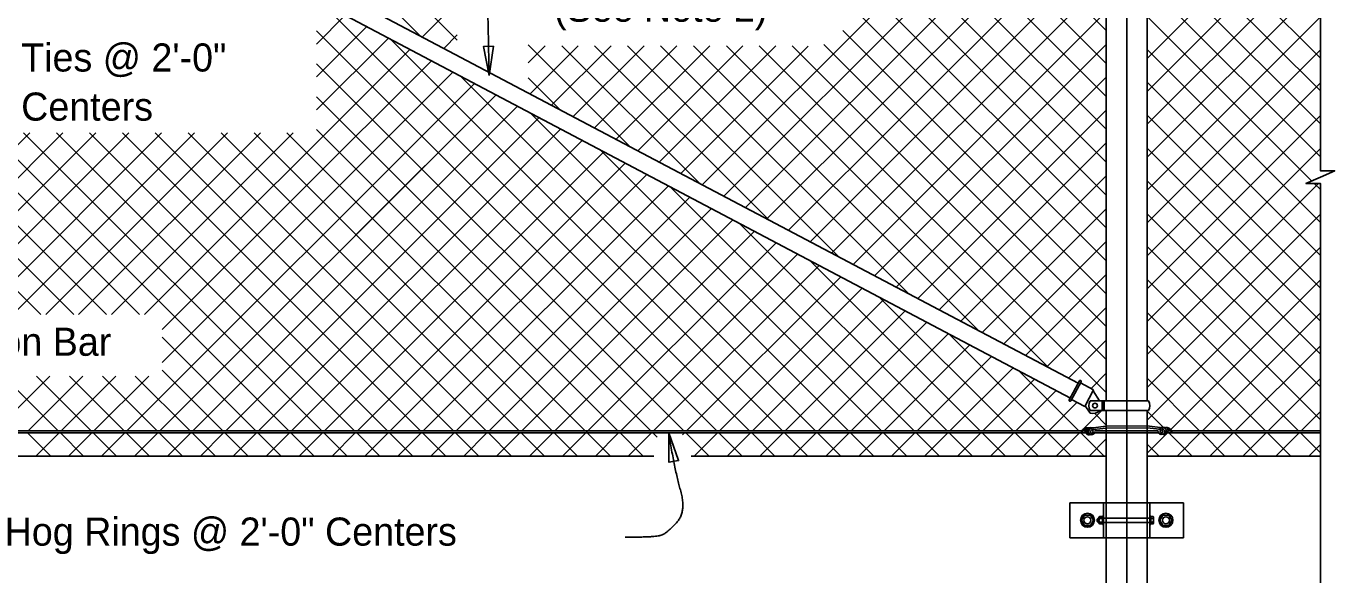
# Model space of a CAD drawing. Extents: x 0 to 41.1, y 0 to 25.9.
# Drawn here: x 6.74 to 16.11, y 16.37 to 20.31 of the extents above; entities that cross this region are included whole.
import ezdxf

# ---------------------------------------------------------------- set-up
doc = ezdxf.new("R2010")
doc.units = 0
for name, color, linetype in [('CL_Major', 7, 'Continuous'), ('Dimension', 7, 'Continuous'), ('Miscellaneous', 7, 'Continuous'), ('SteelMisc', 7, 'Continuous'), ('SteelMisc_h', 7, 'Continuous'), ('SupstrConc', 7, 'Continuous'), ('TextStructures', 7, 'Continuous')]:
    doc.layers.add(name, color=color, linetype=linetype)

msp = doc.modelspace()

# ---------------------------------------------------------------- linework, layer by layer
at = {"layer": 'CL_Major'}
msp.add_line((14.615, 25.0052), (14.615, 14.7584), dxfattribs=at)
at = {"layer": 'Dimension'}
for points in [[(16.002, 23.2265), (16.002, 21.2702), (16.1053, 21.2702), (16.002, 21.2252), (15.8987, 21.1802), (16.002, 21.1802), (16.002, 20.2867)], [(16.002, 20.2867), (16.002, 19.2689), (16.1053, 19.2689), (16.002, 19.2239), (15.8987, 19.1789), (16.002, 19.1789), (16.002, 16.9746)], [(16.002, 17.2246), (16.002, 15.3737), (16.1053, 15.3737), (16.002, 15.3287), (15.8987, 15.2837), (16.002, 15.2837), (16.002, 12.9339)]]:
    msp.add_lwpolyline(points, dxfattribs=at)
for points in [[(10.0503, 19.9529), (10.0815, 20.1618), (10.011, 20.1604)], [(11.336, 17.3912), (11.3376, 17.18), (11.4071, 17.1923)]]:
    msp.add_lwpolyline(points, close=True, dxfattribs=at)
for points in [[(6.6174, 20.081), (6.4865, 20.0669), (6.3036, 20.1341), (6.3121, 20.4608), (6.945, 21.4806)], [(10.4281, 20.8052), (10.1586, 20.8133), (10.0405, 20.6549), (10.0376, 20.5337), (10.0422, 20.3659), (10.0503, 19.9529)], [(11.0247, 16.6442), (11.2476, 16.6407), (11.3325, 16.6797), (11.4633, 16.8284), (11.3785, 17.1258), (11.336, 17.3911)]]:
    msp.add_open_spline(points, degree=2, dxfattribs=at)
at = {"layer": 'Miscellaneous'}
for p, q in [((6.7499, 23.0431), (9.5571, 20.2359)), ((6.9856, 23.0431), (9.8224, 20.2063)), ((10.5211, 23.0431), (14.4692, 19.095)), ((10.7568, 23.0431), (14.4692, 19.3307)), ((10.9925, 23.0431), (14.4692, 19.5664)), ((11.2282, 23.0431), (14.4692, 19.8021)), ((11.4639, 23.0431), (14.4692, 20.0378)), ((11.6996, 23.0431), (14.4692, 20.2735)), ((11.5767, 19.1686), (14.4692, 22.0611)), ((11.7309, 19.0871), (14.4692, 21.8254)), ((11.8851, 19.0056), (14.4692, 21.5897)), ((12.0393, 18.9241), (14.4692, 21.354)), ((14.7609, 21.318), (16.002, 20.0769)), ((14.7609, 20.0738), (16.002, 21.3149)), ((4.8859, 21.1359), (8.6158, 17.4059)), ((12.1936, 18.8426), (14.4692, 21.1183)), ((14.7609, 21.0823), (16.002, 19.8412)), ((14.7609, 19.8381), (16.002, 21.0792)), ((4.8859, 20.9002), (7.5472, 18.2388)), ((12.3478, 18.7611), (14.4692, 20.8826)), ((14.7609, 20.8466), (16.002, 19.6055)), ((14.7609, 19.6024), (16.002, 20.8435)), ((4.8859, 20.6644), (7.3115, 18.2388)), ((12.502, 18.6796), (14.4692, 20.6469)), ((12.6449, 20.6836), (14.4692, 18.8593)), ((14.7609, 20.6109), (16.002, 19.3698)), ((14.7609, 19.3667), (16.002, 20.6078)), ((4.8859, 20.4287), (7.0758, 18.2388)), ((8.845, 20.4766), (11.9157, 17.4059)), ((9.572, 20.228), (9.8224, 20.4784)), ((12.6214, 20.4714), (14.4692, 18.6236)), ((8.8145, 20.1777), (9.0206, 20.3838)), ((12.6562, 18.5982), (14.4692, 20.4112)), ((14.7609, 20.3752), (15.9395, 19.1966)), ((14.7609, 19.131), (16.002, 20.3721)), ((8.8145, 19.942), (9.1748, 20.3023)), ((8.8145, 20.2713), (11.68, 17.4059)), ((9.7262, 20.1465), (9.8224, 20.2427)), ((12.5832, 20.2739), (14.4692, 18.3879)), ((4.8876, 20.1913), (6.8401, 18.2388)), ((8.8145, 19.7063), (9.3291, 20.2208)), ((9.3449, 20.2124), (12.1514, 17.4059)), ((10.3288, 20.1713), (11.0567, 19.4434)), ((10.3288, 20.042), (10.4524, 20.1656)), ((10.343, 19.8205), (10.6881, 20.1656)), ((10.4973, 19.7391), (10.9238, 20.1656)), ((10.5702, 20.1656), (11.5565, 19.1793)), ((10.6515, 19.6576), (11.1595, 20.1656)), ((10.6515, 19.6576), (11.1595, 20.1656)), ((10.8057, 19.5761), (11.3952, 20.1656)), ((10.8059, 20.1656), (12.0564, 18.9151)), ((10.9599, 19.4946), (11.6309, 20.1656)), ((11.0416, 20.1656), (12.5562, 18.651)), ((11.1141, 19.4131), (11.8666, 20.1656)), ((11.2683, 19.3316), (12.1023, 20.1656)), ((11.2773, 20.1656), (13.0561, 18.3868)), ((11.4225, 19.2501), (12.3341, 20.1616)), ((11.513, 20.1656), (13.5559, 18.1227)), ((11.7487, 20.1656), (14.0558, 17.8585)), ((11.9844, 20.1656), (14.4692, 17.6808)), ((12.2201, 20.1656), (14.4692, 17.9165)), ((12.4479, 20.1735), (14.4692, 18.1522)), ((12.8104, 18.5167), (14.4692, 20.1755)), ((7.5828, 18.2388), (9.4833, 20.1393)), ((7.7103, 18.1306), (9.6375, 20.0578)), ((14.7609, 20.1395), (16.002, 18.8984)), ((14.7609, 18.8953), (16.002, 20.1364)), ((7.7103, 17.8949), (9.7917, 19.9763)), ((8.8145, 20.0356), (11.4443, 17.4059)), ((9.0917, 19.2763), (9.7917, 19.9763)), ((7.457, 17.4059), (9.9459, 19.8948)), ((9.0917, 19.0406), (9.9459, 19.8948)), ((9.8447, 19.9483), (12.3871, 17.4059)), ((10.3288, 19.9356), (10.5568, 19.7076)), ((12.9646, 18.4352), (14.4692, 19.9398)), ((14.7609, 19.9038), (16.002, 18.6627)), ((14.7609, 18.6596), (16.002, 19.9007)), ((7.6927, 17.4059), (10.1001, 19.8133)), ((8.8145, 19.7999), (11.2086, 17.4059)), ((9.0917, 18.8049), (10.1001, 19.8133)), ((7.9284, 17.4059), (10.2543, 19.7318)), ((10.3445, 19.6841), (12.6228, 17.4059)), ((13.1188, 18.3537), (14.4692, 19.7041)), ((8.1641, 17.4059), (10.4085, 19.6503)), ((14.7609, 19.6681), (16.002, 18.427)), ((14.7609, 18.4239), (16.002, 19.665)), ((5.7273, 18.5047), (6.7626, 19.54)), ((5.8187, 18.3603), (6.9983, 19.54)), ((5.9329, 18.2388), (7.234, 19.54)), ((6.1686, 18.2388), (7.4697, 19.54)), ((6.4043, 18.2388), (7.7055, 19.54)), ((6.64, 18.2388), (7.9412, 19.54)), ((6.7175, 19.54), (8.8515, 17.4059)), ((6.8757, 18.2388), (8.1769, 19.54)), ((6.9532, 19.54), (9.0872, 17.4059)), ((7.1114, 18.2388), (8.4126, 19.54)), ((7.1889, 19.54), (9.3229, 17.4059)), ((7.3471, 18.2388), (8.6483, 19.54)), ((7.4246, 19.54), (9.5586, 17.4059)), ((7.6603, 19.54), (9.7943, 17.4059)), ((7.896, 19.54), (10.03, 17.4059)), ((8.1317, 19.54), (10.2657, 17.4059)), ((8.3674, 19.54), (10.5014, 17.4059)), ((8.3998, 17.4059), (10.5627, 19.5688)), ((8.6031, 19.54), (10.7372, 17.4059)), ((8.8145, 19.5642), (10.9729, 17.4059)), ((8.6355, 17.4059), (10.717, 19.4873)), ((8.8712, 17.4059), (10.8712, 19.4059)), ((10.8444, 19.42), (12.8585, 17.4059)), ((13.273, 18.2722), (14.4692, 19.4684)), ((14.7609, 19.4324), (16.002, 18.1913)), ((14.7609, 18.1882), (16.002, 19.4293)), ((9.1069, 17.4059), (11.0254, 19.3244)), ((9.3426, 17.4059), (11.1796, 19.2429)), ((13.4272, 18.1907), (14.4692, 19.2327)), ((9.5783, 17.4059), (11.3338, 19.1614)), ((11.3442, 19.1559), (13.0942, 17.4059)), ((14.7609, 19.1967), (16.002, 17.9556)), ((14.7609, 17.9525), (15.9873, 19.1789)), ((15.9572, 19.1789), (16.002, 19.1341)), ((9.814, 17.4059), (11.488, 19.0799)), ((10.0497, 17.4059), (11.6422, 18.9984)), ((13.5814, 18.1092), (14.4692, 18.997)), ((14.7609, 18.961), (16.002, 17.7199)), ((14.7609, 17.7168), (16.002, 18.9578)), ((10.2854, 17.4059), (11.7964, 18.9169)), ((10.5211, 17.4059), (11.9506, 18.8354)), ((11.8441, 18.8917), (13.3299, 17.4059)), ((10.639, 17.2881), (12.1048, 18.7539)), ((13.7356, 18.0277), (14.4692, 18.7613)), ((10.9925, 17.4059), (12.2591, 18.6724)), ((14.7609, 18.7253), (16.002, 17.4842)), ((14.7609, 17.4811), (16.002, 18.7221)), ((11.2282, 17.4059), (12.4133, 18.5909)), ((12.3439, 18.6276), (13.5656, 17.4059)), ((11.4639, 17.4059), (12.5675, 18.5094)), ((13.8899, 17.9462), (14.4692, 18.5256)), ((14.7609, 18.4896), (15.8446, 17.4059)), ((14.9303, 17.4148), (16.002, 18.4864)), ((11.6996, 17.4059), (12.7217, 18.428)), ((11.9353, 17.4059), (12.8759, 18.3465)), ((12.8437, 18.3635), (13.8013, 17.4059)), ((14.0441, 17.8647), (14.4692, 18.2899)), ((12.1711, 17.4059), (13.0301, 18.265)), ((12.4068, 17.4059), (13.1843, 18.1835)), ((14.7609, 18.2539), (15.6089, 17.4059)), ((15.1572, 17.4059), (16.002, 18.2507)), ((12.6425, 17.4059), (13.3385, 18.102)), ((13.3436, 18.0993), (14.037, 17.4059)), ((7.7103, 18.0757), (8.3801, 17.4059)), ((12.8782, 17.4059), (13.4927, 18.0205)), ((14.1983, 17.7832), (14.4692, 18.0542)), ((14.7609, 18.0182), (15.3732, 17.4059)), ((15.3929, 17.4059), (16.002, 18.015)), ((13.1139, 17.4059), (13.647, 17.939)), ((7.7103, 17.84), (8.1444, 17.4059)), ((13.3496, 17.4059), (13.8012, 17.8575)), ((13.8434, 17.8352), (14.2727, 17.4059)), ((14.36, 17.7093), (14.4692, 17.8185)), ((6.5142, 17.4059), (6.9059, 17.7976)), ((6.5742, 17.7976), (6.9659, 17.4059)), ((6.7499, 17.4059), (7.1416, 17.7976)), ((6.8099, 17.7976), (7.2016, 17.4059)), ((6.9856, 17.4059), (7.3773, 17.7976)), ((7.0456, 17.7976), (7.4373, 17.4059)), ((7.2213, 17.4059), (7.613, 17.7976)), ((7.2813, 17.7976), (7.673, 17.4059)), ((7.517, 17.7976), (7.9087, 17.4059)), ((13.5853, 17.4059), (13.9554, 17.776)), ((14.7609, 17.7825), (15.1375, 17.4059)), ((15.6286, 17.4059), (16.002, 17.7793)), ((13.821, 17.4059), (14.1096, 17.6945)), ((14.0567, 17.4059), (14.2591, 17.6084)), ((14.3083, 17.4218), (14.4379, 17.5514)), ((14.3836, 17.5307), (14.4692, 17.4451)), ((14.7609, 17.5468), (14.8783, 17.4294)), ((15.8643, 17.4059), (16.002, 17.5436)), ((6.745, 17.3912), (6.9116, 17.2245)), ((6.8042, 17.2245), (6.9709, 17.3912)), ((6.9807, 17.3912), (7.1473, 17.2245)), ((7.0399, 17.2245), (7.2066, 17.3912)), ((7.2164, 17.3912), (7.383, 17.2245)), ((7.2756, 17.2245), (7.4423, 17.3912)), ((7.4521, 17.3912), (7.6187, 17.2245)), ((7.5113, 17.2245), (7.678, 17.3912)), ((7.6878, 17.3912), (7.8544, 17.2245)), ((7.747, 17.2245), (7.9137, 17.3912)), ((7.9235, 17.3912), (8.0901, 17.2245)), ((7.9827, 17.2245), (8.1494, 17.3912)), ((8.1592, 17.3912), (8.3258, 17.2245)), ((8.2184, 17.2245), (8.3851, 17.3912)), ((8.3949, 17.3912), (8.5615, 17.2245)), ((8.4541, 17.2245), (8.6208, 17.3912)), ((8.6306, 17.3912), (8.7972, 17.2245)), ((8.6898, 17.2245), (8.8565, 17.3912)), ((8.8663, 17.3912), (9.0329, 17.2245)), ((8.9255, 17.2245), (9.0922, 17.3912)), ((9.102, 17.3912), (9.2687, 17.2245)), ((9.1612, 17.2245), (9.3279, 17.3912)), ((9.3377, 17.3912), (9.5044, 17.2245)), ((9.3969, 17.2245), (9.5636, 17.3912)), ((9.5734, 17.3912), (9.7401, 17.2245)), ((9.6326, 17.2245), (9.7993, 17.3912)), ((9.8091, 17.3912), (9.9758, 17.2245)), ((9.8683, 17.2245), (10.035, 17.3912)), ((10.0448, 17.3912), (10.2115, 17.2245)), ((10.104, 17.2245), (10.2707, 17.3912)), ((10.2805, 17.3912), (10.4472, 17.2245)), ((10.3397, 17.2245), (10.5064, 17.3912)), ((10.5162, 17.3912), (10.6829, 17.2245)), ((10.5754, 17.2245), (10.7421, 17.3912)), ((10.7519, 17.3912), (10.9186, 17.2245)), ((10.8111, 17.2245), (10.9778, 17.3912)), ((10.9876, 17.3912), (11.1543, 17.2245)), ((11.0468, 17.2245), (11.2135, 17.3912)), ((11.2233, 17.3912), (11.2544, 17.36)), ((11.4351, 17.3771), (11.4492, 17.3912)), ((11.459, 17.3912), (11.6257, 17.2245)), ((11.5182, 17.2245), (11.6849, 17.3912)), ((11.6947, 17.3912), (11.8614, 17.2245)), ((11.7539, 17.2245), (11.9206, 17.3912)), ((11.9304, 17.3912), (12.0971, 17.2245)), ((11.9896, 17.2245), (12.1563, 17.3912)), ((12.1661, 17.3912), (12.3328, 17.2245)), ((12.2253, 17.2245), (12.392, 17.3912)), ((12.4018, 17.3912), (12.5685, 17.2245)), ((12.461, 17.2245), (12.6277, 17.3912)), ((12.6375, 17.3912), (12.8042, 17.2245)), ((12.6967, 17.2245), (12.8634, 17.3912)), ((12.8732, 17.3912), (13.0399, 17.2245)), ((12.9324, 17.2245), (13.0991, 17.3912)), ((13.1089, 17.3912), (13.2756, 17.2245)), ((13.1681, 17.2245), (13.3348, 17.3912)), ((13.3446, 17.3912), (13.5113, 17.2245)), ((13.4038, 17.2245), (13.5705, 17.3912)), ((13.5803, 17.3912), (13.747, 17.2245)), ((13.6396, 17.2245), (13.8062, 17.3912)), ((13.816, 17.3912), (13.9827, 17.2245)), ((13.8753, 17.2245), (14.0419, 17.3912)), ((14.0517, 17.3912), (14.2184, 17.2245)), ((14.111, 17.2245), (14.2776, 17.3912)), ((14.2874, 17.3912), (14.4541, 17.2245)), ((14.2924, 17.4059), (14.296, 17.4095)), ((14.3467, 17.2245), (14.4692, 17.3471)), ((14.7609, 17.2454), (14.8992, 17.3837)), ((14.9165, 17.3912), (15.0832, 17.2245)), ((14.9757, 17.2245), (15.1424, 17.3912)), ((15.1522, 17.3912), (15.3189, 17.2245)), ((15.2114, 17.2245), (15.3781, 17.3912)), ((15.3879, 17.3912), (15.5546, 17.2245)), ((15.4471, 17.2245), (15.6138, 17.3912)), ((15.6236, 17.3912), (15.7903, 17.2245)), ((15.6828, 17.2245), (15.8495, 17.3912)), ((15.8593, 17.3912), (16.002, 17.2485)), ((14.7641, 17.3078), (14.8475, 17.2245)), ((15.9185, 17.2245), (16.002, 17.3079)), ((14.4075, 16.7575), (14.4075, 16.7696)), ((14.4132, 16.7575), (14.4132, 16.7696))]:
    msp.add_line(p, q, dxfattribs=at)
at = {"layer": 'SteelMisc'}
for p, q in [((14.4692, 17.6192), (14.4692, 23.2644)), ((14.7609, 17.6192), (14.7609, 23.2644)), ((14.2677, 17.7466), (5.0181, 22.6346)), ((14.2117, 17.6406), (4.962, 22.5285)), ((14.2041, 17.6263), (14.2766, 17.7635)), ((14.216, 17.6201), (14.2885, 17.7572)), ((14.2843, 17.7493), (14.3786, 17.6995)), ((14.3149, 17.5789), (14.2206, 17.6287)), ((14.3149, 17.5789), (14.3786, 17.6995)), ((14.7722, 17.6193), (14.3525, 17.6193)), ((14.3744, 17.6914), (14.4213, 17.6197)), ((14.3184, 17.5855), (14.3531, 17.5323)), ((14.7721, 17.5514), (14.3525, 17.5514)), ((14.4349, 17.613), (14.4584, 17.613)), ((14.4349, 17.6032), (14.4584, 17.6032)), ((14.4349, 17.5914), (14.4584, 17.5914)), ((14.4349, 17.5797), (14.4584, 17.5797)), ((14.4349, 17.5688), (14.4584, 17.5688)), ((14.4349, 17.5593), (14.4584, 17.5593)), ((14.4692, 16.8894), (14.4692, 17.5514)), ((14.7609, 16.8894), (14.7609, 17.5514)), ((14.4692, 17.4385), (14.3743, 17.4274)), ((14.4692, 17.4385), (14.7604, 17.4402)), ((14.7604, 17.4402), (14.8547, 17.4291)), ((4.923, 17.3912), (14.3207, 17.3912)), ((4.9243, 17.4059), (14.2941, 17.4059)), ((14.304, 17.4059), (14.3172, 17.4059)), ((14.4692, 17.424), (14.3766, 17.4145)), ((14.3856, 17.3912), (14.4692, 17.3912)), ((14.387, 17.4059), (14.4692, 17.4059)), ((14.4692, 17.424), (14.7604, 17.4257)), ((14.7604, 17.4257), (14.8525, 17.4163)), ((14.7609, 17.4059), (14.8413, 17.4059)), ((14.7609, 17.3912), (14.8439, 17.3912)), ((14.9059, 17.3912), (16.002, 17.3912)), ((14.9116, 17.4059), (14.9269, 17.4059)), ((14.9353, 17.4059), (16.002, 17.4059)), ((14.2091, 16.8894), (15.021, 16.8894)), ((14.2091, 16.6394), (14.2091, 16.8894)), ((14.4484, 16.8894), (14.4484, 16.6394)), ((14.7817, 16.8894), (14.7817, 16.6394)), ((15.021, 16.8894), (15.021, 16.6394)), ((14.4047, 16.7724), (14.4103, 16.7789)), ((14.4047, 16.7547), (14.4047, 16.7724)), ((14.4103, 16.7789), (14.4168, 16.7789)), ((14.4103, 16.749), (14.4103, 16.7789)), ((14.4168, 16.7823), (14.4168, 16.7465)), ((14.4215, 16.7774), (14.4418, 16.7774)), ((14.4217, 16.7904), (14.4418, 16.7904)), ((14.4418, 16.7947), (14.4418, 16.734)), ((14.4418, 16.7947), (14.4484, 16.7947)), ((14.4418, 16.7904), (14.4418, 16.7384)), ((14.788, 16.7947), (14.782, 16.7947)), ((14.788, 16.7947), (14.788, 16.734)), ((14.8027, 16.7903), (14.788, 16.7903)), ((14.8028, 16.7773), (14.788, 16.7773)), ((14.8078, 16.745), (14.8078, 16.7838)), ((14.4047, 16.7547), (14.4103, 16.749)), ((14.4103, 16.749), (14.4168, 16.749)), ((14.4215, 16.7514), (14.4418, 16.7514)), ((14.4218, 16.7384), (14.4418, 16.7384)), ((14.4418, 16.734), (14.4484, 16.734)), ((14.788, 16.734), (14.782, 16.734)), ((14.8028, 16.7514), (14.788, 16.7514)), ((14.8027, 16.7384), (14.788, 16.7384)), ((15.021, 16.6394), (14.2091, 16.6394)), ((14.4692, 16.6394), (14.4692, 15.3894)), ((14.7609, 16.6394), (14.7609, 15.3894))]:
    msp.add_line(p, q, dxfattribs=at)
for points in [[(14.3124, 16.8019), (14.3557, 16.8019), (14.3774, 16.7644), (14.3557, 16.7269), (14.3124, 16.7269), (14.2907, 16.7644)], [(14.8744, 16.8019), (14.9177, 16.8019), (14.9394, 16.7644), (14.9177, 16.7269), (14.8744, 16.7269), (14.8527, 16.7644)]]:
    msp.add_lwpolyline(points, close=True, dxfattribs=at)
for centre, radius in [((14.3341, 16.7644), 0.05), ((14.3341, 16.7644), 0.025), ((14.896, 16.7644), 0.05), ((14.896, 16.7644), 0.025)]:
    msp.add_circle(centre, radius, dxfattribs=at)
for centre, radius, start, end in [((14.2827, 17.7605), 0.00673, 332.14902, 152.14902), ((14.2102, 17.6233), 0.00673, 152.14902, 332.14902), ((14.4234, 16.7838), 0.00674, 104.48908, 254.18889), ((14.4363, 16.7644), 0.0196, 138.62797, 221.37203), ((14.801, 16.7838), 0.00673, 285.7823, 75.54039), ((14.7881, 16.7644), 0.0196, 318.62797, 41.37203), ((14.4234, 16.7449), 0.00673, 105.7823, 255.54039), ((14.801, 16.7449), 0.00674, 284.48908, 74.18889)]:
    msp.add_arc(centre, radius, start, end, dxfattribs=at)
for centre, major_axis, ratio, start_param, end_param in [((14.4217, 17.5856), (-0.0776, 0), 0.957868, 5.810211, 6.75616), ((14.7031, 17.5855), (0.0776, 0), 0.957868, 5.807767, 6.754779), ((14.3697, 17.6006), (0.0647, -0.0342), 0.957868, 4.95193, 6.011789), ((14.3283, 17.3916), (0.0373, 0), 0.957868, 1.486836, 3.108042), ((14.3408, 17.4061), (0.023, 0), 0.957868, 1.29026, 2.970541), ((14.3595, 17.4007), (0.0295, 0), 0.957868, 1.220941, 4.039556), ((14.8556, 17.4043), (0.0303, -0.0108), 0.724765, 6.241815, 8.212701), ((14.8691, 17.4025), (-0.0295, 0), 0.957868, 2.243629, 5.062245), ((14.8879, 17.4079), (-0.023, 0), 0.957868, 3.312645, 4.992926), ((14.9004, 17.3934), (-0.0373, 0), 0.957868, 3.175144, 4.79635), ((14.3494, 17.3519), (-0.0724, 0), 0.957868, 5.162149, 5.652106), ((14.3419, 17.4036), (-0.0249, 0), 0.957868, 6.009018, 7.089857), ((14.3433, 17.3996), (0.0231, 0), 0.957868, 3.779554, 4.879821), ((14.373, 17.4025), (-0.0303, -0.0108), 0.724765, 4.35367, 6.324556), ((14.3494, 17.3939), (0.0206, -0.0021), 0.798607, 4.32653, 5.220153), ((14.3629, 17.3939), (0.0206, -0.0021), 0.798607, 3.333154, 5.220153), ((14.3697, 17.3985), (-0.0139, 0), 0.957868, 5.22362, 6.905413), ((14.364, 17.3961), (-0.00795, 0), 0.957868, 6.140374, 9.314262), ((14.3781, 17.3896), (-0.0259, 0), 0.957868, 4.777514, 5.62749), ((14.3624, 17.4019), (0.0119, 0), 0.957868, 5.725876, 7.416677), ((14.3555, 17.4127), (0.0391, 0), 0.957868, 5.082588, 5.41974), ((14.3624, 17.4019), (0.0119, 0), 0.957868, 5.639684, 5.723117), ((14.3626, 17.4006), (0.0251, 0), 0.957868, 5.531357, 6.227833), ((14.3626, 17.4006), (0.0251, 0), 0.957868, 0.407687, 0.609214), ((14.8661, 17.4024), (-0.0251, 0), 0.957868, 0.055352, 0.751829), ((14.8661, 17.4024), (-0.0251, 0), 0.957868, 5.673972, 5.875498), ((14.8732, 17.4144), (-0.0391, 0), 0.957868, 0.863445, 1.200597), ((14.8506, 17.3914), (0.0259, 0), 0.957868, 0.655696, 1.505671), ((14.8663, 17.4036), (-0.0119, 0), 0.957868, 5.149694, 6.840495), ((14.8663, 17.4036), (-0.0119, 0), 0.957868, 0.560069, 0.643501), ((14.8646, 17.3979), (0.00795, 0), 0.957868, 3.252108, 6.425997), ((14.8658, 17.3957), (-0.0206, -0.0021), 0.798607, 1.063032, 2.950031), ((14.859, 17.4002), (0.0139, 0), 0.957868, 5.660958, 7.342751), ((14.8792, 17.3957), (-0.0206, -0.0021), 0.798607, 1.063032, 1.956656), ((14.8853, 17.4014), (-0.0231, 0), 0.957868, 1.403365, 2.503632), ((14.8867, 17.4054), (0.0249, 0), 0.957868, 5.476514, 6.557353), ((14.8792, 17.3537), (0.0724, 0), 0.957868, 0.631079, 1.121037)]:
    msp.add_ellipse(centre, major_axis=major_axis, ratio=ratio, start_param=start_param, end_param=end_param, dxfattribs=at)
msp.add_ellipse((14.3884, 17.586), major_axis=(0.0178, 0), ratio=0.957868, dxfattribs=at)
at = {"layer": 'SteelMisc_h'}
for p, q in [((14.4692, 17.4059), (14.7609, 17.4059)), ((14.4692, 17.3912), (14.7609, 17.3912)), ((14.4692, 16.8894), (14.4692, 16.6394)), ((14.7609, 16.8894), (14.7609, 16.6394)), ((14.7817, 16.7789), (14.4168, 16.7789)), ((14.4168, 16.749), (14.7817, 16.749))]:
    msp.add_line(p, q, dxfattribs=at)
at = {"layer": 'SupstrConc'}
for p, q in [((4.7609, 17.2245), (11.2293, 17.2245)), ((11.4981, 17.2245), (14.4692, 17.2245)), ((14.7609, 17.2245), (16.002, 17.2245))]:
    msp.add_line(p, q, dxfattribs=at)

# ---------------------------------------------------------------- texts
at = {"layer": 'Dimension'}
for s, p in [('Ties @ 2\'-0" ', (6.6999, 19.9805)), ('Centers', (6.6999, 19.6285))]:
    msp.add_text(s, height=0.2016, dxfattribs=at).set_placement(p)
at = {"layer": 'TextStructures'}
for s, p in [('(See Note 2)', (10.5146, 20.3375)), ('Tension Bar', (5.892, 17.9432)), ('Hog Rings @ 2\'-0" Centers', (6.5816, 16.5823))]:
    msp.add_text(s, height=0.2016, dxfattribs=at).set_placement(p)

doc.saveas('drawing.dxf')
